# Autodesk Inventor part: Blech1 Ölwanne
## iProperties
Author: rebem
Created: 2004-04
Part Number: Blech1 Ölwanne
Material: Standard
Document SubType Name: Blech
Designer: rebem
Control State: 0
Master: False
Checked Out: False
PropertySet Name: Design Tracking Control
Shininess: 20.0
PropertySet Name: _Private Model Information
Density: 1.0
Volumn: 3284.414021789589
Area: 22106.687371974065
PropertySet Name: Model Information
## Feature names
1. Extrusion1
2. Verjüngungskante1
3. Fase1 [Chamfer]
4. Rundung1 [Fillet]
5. Rundung2 [Fillet]
6. Extrusion5
7. Extrusion6
8. ExtrusionAbwicklung1
